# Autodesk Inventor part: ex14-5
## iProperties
Author: J. DESIGNER
Revision Number: A
Shininess: 64.0
Angle Display Precision: 2
Document Length Units: 11272
Document Angle Units: 11286
Document Time Units: 11279
Document Mass Units: 11290
Document Length Units Precision: 3
Document Angle Units Precision: 2
Compacted: False
PropertySet Name: _Private Model Information
Created: 2001-10
Part Number: ex14-5
Description: CLAMP, RISER BAR
Document SubType Name: Modeling
Designer: J. DESIGNER
Control State: 0
Master: False
Checked Out: False
PropertySet Name: Design Tracking Control
Density: 0.0
Volumn: 0.0
Area: 0.0
PropertySet Name: Model Information
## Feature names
1. Extrusion1
2. Hole1
3. Hole2
